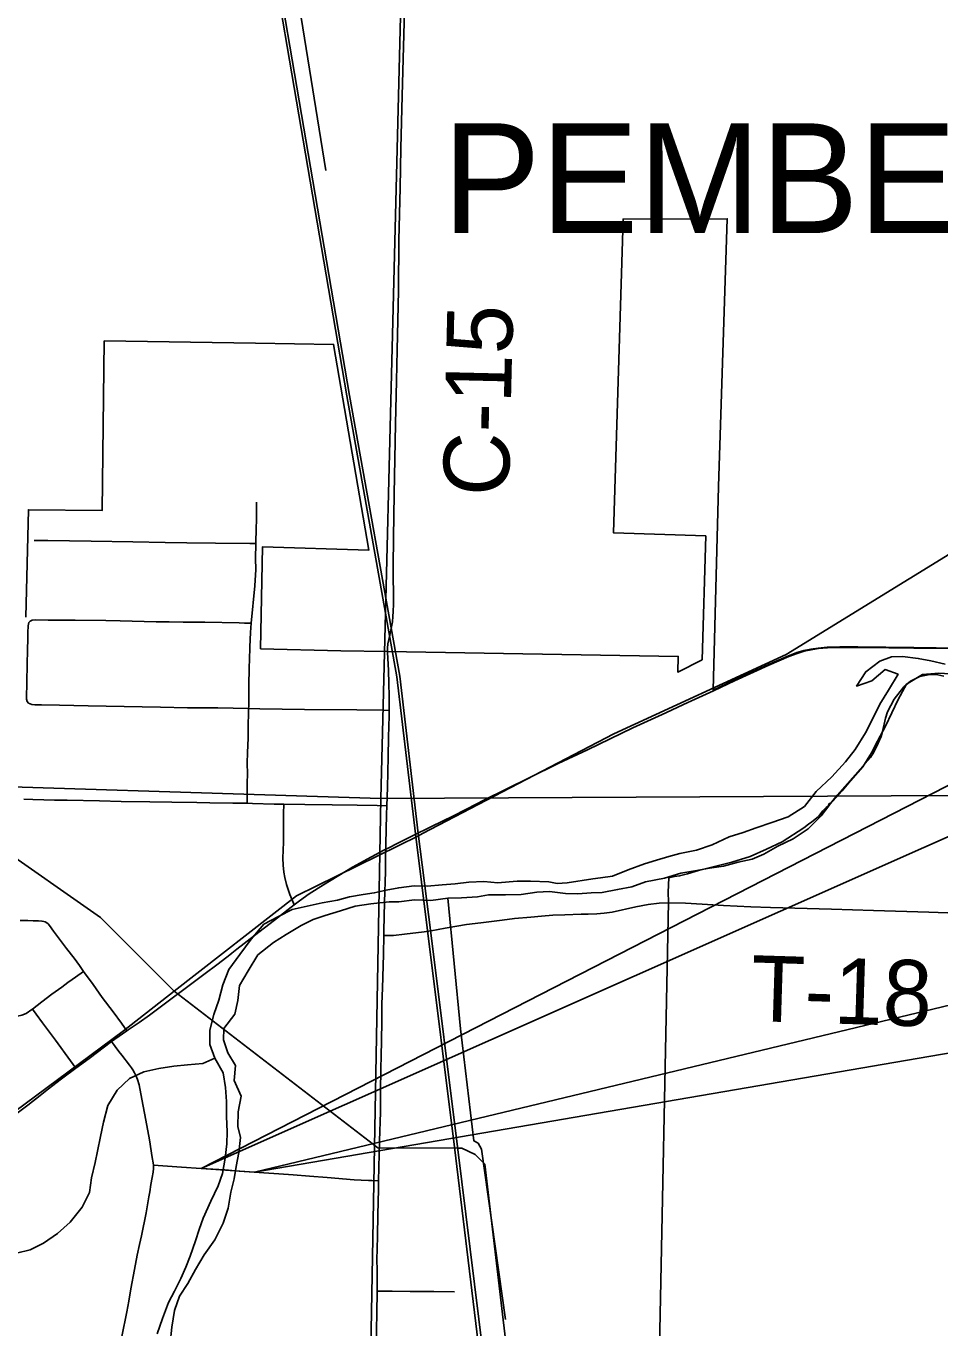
# Model space of a CAD drawing. Extents: x -8.3 to 42.1, y 0 to 22.
# Drawn here: x 5.562 to 6.351, y 16.882 to 18.005 of the extents above; entities that cross this region are included whole.
import ezdxf

# ---------------------------------------------------------------- set-up
doc = ezdxf.new("R2010")
doc.units = 0
for name, color, linetype in [('GM_X_City_Street', 7, 'Continuous'), ('GM_X_Corporation', 7, 'Continuous'), ('GM_X_Corporation_Text', 7, 'Continuous'), ('GM_X_County_Road', 7, 'Continuous'), ('GM_X_County_Road_Text', 7, 'Continuous'), ('GM_X_Major_River', 7, 'Continuous'), ('GM_X_Minor_River', 7, 'Continuous'), ('GM_X_Rail_Line', 7, 'Continuous'), ('GM_X_Section', 7, 'Continuous'), ('GM_X_State_Route', 7, 'Continuous'), ('GM_X_Township_Road', 7, 'Continuous'), ('GM_X_Township_Road_Text', 7, 'Continuous'), ('SH_Text', 7, 'Continuous')]:
    doc.layers.add(name, color=color, linetype=linetype)

msp = doc.modelspace()

# ---------------------------------------------------------------- linework, layer by layer
at = {"layer": 'GM_X_City_Street'}
for points in [[(5.7529, 17.3344), (5.7529, 17.3369), (5.7529, 17.3431), (5.753, 17.3474), (5.7531, 17.3525), (5.7533, 17.3588), (5.7531, 17.3697), (5.7534, 17.3773), (5.7536, 17.3852), (5.7538, 17.39), (5.7538, 17.3977), (5.7542, 17.4161), (5.7543, 17.4179), (5.7545, 17.4366), (5.7548, 17.4506), (5.7553, 17.468), (5.7553, 17.4693), (5.7558, 17.4817), (5.7564, 17.4896), (5.7595, 17.522), (5.7604, 17.5361), (5.7603, 17.5454), (5.7605, 17.5583), (5.7608, 17.5719), (5.7609, 17.5782), (5.7611, 17.594)], [(5.5693, 17.5609), (5.581, 17.5611), (5.6184, 17.5605), (5.6542, 17.56), (5.6822, 17.5594), (5.7009, 17.5591), (5.7258, 17.5586), (5.7554, 17.5583), (5.7605, 17.5583)], [(5.5644, 17.4206), (5.5631, 17.4221), (5.5626, 17.4241), (5.5629, 17.4397), (5.5634, 17.4672), (5.5637, 17.4755), (5.5637, 17.4816), (5.564, 17.4874), (5.5647, 17.4902), (5.5657, 17.4915)], [(5.5657, 17.4915), (5.5674, 17.4924), (5.5702, 17.4926), (5.5812, 17.4924), (5.6045, 17.4923), (5.631, 17.4919), (5.6434, 17.4917), (5.6744, 17.4909), (5.6857, 17.4908), (5.6978, 17.4907), (5.7165, 17.4905), (5.746, 17.49), (5.7507, 17.4898), (5.7564, 17.4896)], [(5.5644, 17.4206), (5.5671, 17.4195), (5.5699, 17.4192), (5.5755, 17.4192), (5.591, 17.4189), (5.6159, 17.4185), (5.6625, 17.4175), (5.6781, 17.4173), (5.7014, 17.4168), (5.7278, 17.4166), (5.7542, 17.4161), (5.7638, 17.4159), (5.8026, 17.4154), (5.8477, 17.4149), (5.8701, 17.4146), (5.8755, 17.4145)], [(5.5603, 17.3378), (5.568, 17.3376), (5.5774, 17.3374), (5.5867, 17.3372), (5.5976, 17.337), (5.6256, 17.3364), (5.6442, 17.336), (5.6691, 17.3355), (5.6881, 17.3354), (5.7096, 17.335), (5.7208, 17.3348), (5.7406, 17.3346), (5.7529, 17.3344), (5.7577, 17.3343), (5.7764, 17.3337), (5.7845, 17.3336), (5.8028, 17.3334), (5.8262, 17.3331), (5.8479, 17.3327), (5.8651, 17.3325), (5.8736, 17.3323)], [(5.7936, 17.2467), (5.7914, 17.2518), (5.7897, 17.2557), (5.7869, 17.2644), (5.7854, 17.2704), (5.7846, 17.2749), (5.784, 17.2809), (5.7838, 17.287), (5.7844, 17.3009), (5.7844, 17.3256), (5.7845, 17.3336)], [(5.6493, 17.1381), (5.6446, 17.1446), (5.6373, 17.1545), (5.628, 17.1669), (5.62, 17.1782), (5.6119, 17.1894), (5.6082, 17.1945), (5.6036, 17.2007), (5.597, 17.2092), (5.5859, 17.2241), (5.5823, 17.2291), (5.5813, 17.2303), (5.5801, 17.2312), (5.5788, 17.232), (5.5774, 17.2325), (5.5759, 17.2328), (5.5728, 17.2331), (5.5713, 17.233), (5.5682, 17.2331), (5.5638, 17.2332), (5.561, 17.2332), (5.557, 17.2333)], [(5.5549, 17.1508), (5.5585, 17.1516), (5.5623, 17.1532), (5.5671, 17.1564), (5.5679, 17.1569), (5.5758, 17.163), (5.5844, 17.1696), (5.5931, 17.1757), (5.5983, 17.1797), (5.602, 17.1824), (5.6098, 17.1878), (5.6119, 17.1894)], [(5.6052, 17.1058), (5.6005, 17.1123), (5.5877, 17.13), (5.5765, 17.145), (5.571, 17.1526), (5.5679, 17.1569)], [(5.6722, 17.0222), (5.6761, 17.0219), (5.6963, 17.0205), (5.7134, 17.0195), (5.7336, 17.0181), (5.746, 17.0172), (5.7803, 17.0148), (5.7927, 17.0139), (5.8068, 17.0127), (5.8221, 17.0116), (5.8454, 17.0097), (5.8515, 17.0093), (5.8576, 17.009), (5.8607, 17.0089), (5.8663, 17.0086)], [(5.8651, 16.9135), (5.8692, 16.9135), (5.8781, 16.9135), (5.8937, 16.9133), (5.9141, 16.9133), (5.9319, 16.9131)]]:
    msp.add_lwpolyline(points, dxfattribs=at)
at = {"layer": 'GM_X_Corporation'}
for points in [[(5.5621, 17.4948), (5.5642, 17.5875), (5.628, 17.5869), (5.6297, 17.7331), (5.7603, 17.7313), (5.8275, 17.7301), (5.858, 17.5527), (5.7662, 17.5555), (5.7645, 17.4676), (5.8339, 17.466), (5.8739, 17.4653), (6.1249, 17.4611), (6.1245, 17.4475), (6.1457, 17.4581), (6.1487, 17.5649), (6.0691, 17.5676), (6.0774, 17.8383), (6.1672, 17.8385), (6.1596, 17.6077), (6.1552, 17.4319), (6.1732, 17.4406), (6.2029, 17.4541), (6.22, 17.4615), (6.2274, 17.4643), (6.2334, 17.4661), (6.2395, 17.4674), (6.2457, 17.4683), (6.2535, 17.4689), (6.2644, 17.4693), (6.28, 17.4694), (6.3281, 17.4687), (6.3669, 17.4683)], [(6.354, 17.4441), (6.349, 17.4451), (6.3436, 17.4454), (6.3406, 17.4452), (6.3335, 17.4436), (6.3255, 17.4397), (6.3197, 17.4348), (6.3113, 17.4243), (6.3056, 17.4133), (6.3038, 17.4079), (6.3012, 17.3962), (6.3, 17.3921), (6.2987, 17.3887), (6.2976, 17.3861), (6.2947, 17.3802), (6.2929, 17.3771), (6.2929, 17.3766), (6.2923, 17.3763), (6.2908, 17.374), (6.2622, 17.3414), (6.2563, 17.3341), (6.2553, 17.3341), (6.2545, 17.3324), (6.2538, 17.3315), (6.2527, 17.3307), (6.2497, 17.328), (6.2459, 17.3231), (6.2443, 17.3214), (6.2403, 17.3183), (6.2374, 17.3164), (6.2334, 17.3131), (6.2147, 17.3012), (6.2011, 17.2948), (6.1871, 17.2885), (6.1712, 17.2837), (6.1423, 17.2764), (6.133, 17.2735), (6.1261, 17.2717), (6.1216, 17.2711), (6.1169, 17.2702), (6.1164, 17.2578), (6.1166, 17.2491), (6.1082, 16.8369)]]:
    msp.add_lwpolyline(points, dxfattribs=at)
at = {"layer": 'GM_X_County_Road'}
for points in [[(5.8741, 17.4647), (5.8741, 17.4681), (5.8744, 17.4718), (5.8761, 17.4793), (5.8783, 17.4909), (5.8787, 17.4955), (5.8791, 17.4997), (5.8793, 17.506), (5.879, 17.5386), (5.8794, 17.5635), (5.8798, 17.6009), (5.881, 17.6615), (5.8818, 17.6988), (5.8823, 17.7253), (5.8835, 17.7766), (5.884, 17.8201), (5.8851, 17.8652), (5.8857, 17.8995), (5.8868, 17.9445), (5.889, 18.0297)], [(5.8755, 17.4145), (5.8755, 17.4268), (5.8752, 17.4376), (5.8749, 17.449), (5.8741, 17.4647)], [(5.8736, 17.3323), (5.8741, 17.348), (5.8746, 17.3743), (5.875, 17.3913), (5.8755, 17.4098), (5.8755, 17.4145)], [(5.8726, 17.2947), (5.8727, 17.2991), (5.8733, 17.3248), (5.8736, 17.3323)], [(5.8708, 17.2204), (5.8708, 17.2243), (5.8715, 17.2492), (5.8723, 17.2756), (5.8723, 17.28), (5.8723, 17.2884), (5.8726, 17.2947)], [(5.8663, 17.0086), (5.8671, 17.0433), (5.8679, 17.0681), (5.8679, 17.085), (5.8683, 17.1065), (5.8685, 17.1157), (5.8691, 17.1452), (5.8693, 17.1607), (5.8696, 17.1685), (5.8699, 17.1747), (5.8705, 17.2041), (5.8708, 17.2204)], [(5.6532, 17.1062), (5.6516, 17.1085), (5.6448, 17.1171), (5.6423, 17.1203), (5.6359, 17.129)], [(5.6722, 17.0222), (5.672, 17.0242), (5.6711, 17.0288), (5.6686, 17.0441), (5.6664, 17.0564), (5.6613, 17.0839), (5.6597, 17.0915), (5.6584, 17.0961), (5.6573, 17.0991), (5.6559, 17.1019), (5.6543, 17.1046), (5.6532, 17.1062)], [(5.6449, 16.8745), (5.6492, 16.8958), (5.6508, 16.905), (5.6527, 16.9157), (5.6559, 16.9324), (5.6582, 16.9446), (5.6601, 16.9537), (5.6617, 16.9613), (5.6657, 16.9811), (5.6682, 16.9948), (5.6689, 16.9993), (5.6699, 17.0055), (5.6709, 17.0116), (5.6718, 17.0162), (5.6722, 17.0194), (5.6722, 17.0222)], [(5.8651, 16.9135), (5.8651, 16.9176), (5.8652, 16.9316), (5.865, 16.9409), (5.8651, 16.9502), (5.8654, 16.961), (5.8656, 16.9796), (5.8662, 17.0014), (5.8663, 17.0086)], [(5.8638, 16.8392), (5.8649, 16.8943), (5.8651, 16.9135)]]:
    msp.add_lwpolyline(points, dxfattribs=at)
at = {"layer": 'GM_X_Major_River'}
for points in [[(6.3554, 17.4545), (6.3429, 17.4571), (6.332, 17.4593), (6.3184, 17.4611), (6.3089, 17.4606), (6.299, 17.457), (6.2867, 17.4478), (6.2788, 17.4355), (6.2921, 17.4401), (6.3034, 17.4497), (6.3146, 17.4456), (6.3063, 17.4318), (6.2988, 17.4198), (6.2929, 17.4075), (6.2865, 17.3951), (6.2777, 17.3809), (6.2692, 17.3701), (6.2575, 17.3571), (6.244, 17.3445), (6.2338, 17.3315), (6.2199, 17.3227), (6.2058, 17.3177), (6.1921, 17.3131), (6.181, 17.3092), (6.1688, 17.3053), (6.1542, 17.2985)], [(5.9759, 17.2554), (5.9895, 17.2558), (6.0028, 17.2578), (6.0138, 17.2583), (6.0277, 17.2567), (6.0383, 17.2562), (6.0498, 17.257), (6.0593, 17.2575), (6.0726, 17.2599), (6.0848, 17.2622), (6.0966, 17.2665), (6.113, 17.2699), (6.1271, 17.2741), (6.1393, 17.2761), (6.1518, 17.2784), (6.164, 17.28), (6.1766, 17.2835), (6.1887, 17.2863), (6.1987, 17.2906), (6.211, 17.2975), (6.224, 17.3036), (6.2371, 17.3124), (6.2484, 17.3236), (6.2558, 17.3332), (6.2663, 17.3451), (6.2737, 17.3538), (6.2843, 17.3658), (6.2917, 17.3779), (6.2969, 17.388), (6.3037, 17.4008), (6.3148, 17.424), (6.322, 17.4371), (6.3358, 17.4455), (6.3499, 17.4467), (6.3597, 17.4461)], [(6.1542, 17.2985), (6.1408, 17.2939), (6.1264, 17.2912), (6.1168, 17.2884), (6.1062, 17.2852), (6.0959, 17.2821), (6.0817, 17.2771), (6.0683, 17.2714), (6.0579, 17.2702), (6.0512, 17.2693), (6.029, 17.2658), (6.0206, 17.2653), (6.0133, 17.2666), (5.9975, 17.2671), (5.9859, 17.2671), (5.9792, 17.2667), (5.9693, 17.2658), (5.9573, 17.2668), (5.9444, 17.2664), (5.9326, 17.2648), (5.9212, 17.2639), (5.9082, 17.2628), (5.8971, 17.2631), (5.8838, 17.2615), (5.873, 17.2594), (5.8627, 17.257), (5.8532, 17.2557), (5.8414, 17.2537), (5.8308, 17.2509), (5.8178, 17.2486), (5.7919, 17.2428), (5.78, 17.2366), (5.7674, 17.2301), (5.7564, 17.2171), (5.7467, 17.204), (5.7372, 17.191), (5.732, 17.1778), (5.7286, 17.1646), (5.7242, 17.1522), (5.7208, 17.1386), (5.7209, 17.1264), (5.7251, 17.1146)], [(5.6865, 16.8688), (5.6879, 16.8825), (5.6902, 16.8968), (5.6947, 16.9092), (5.7017, 16.9201), (5.7085, 16.9324), (5.716, 16.9448), (5.725, 16.9578), (5.7322, 16.9721), (5.7367, 16.9853), (5.7389, 16.9989), (5.7419, 17.0106), (5.7436, 17.0212), (5.7458, 17.0332), (5.7473, 17.0461), (5.7449, 17.0557), (5.7452, 17.0682), (5.7478, 17.0818), (5.7417, 17.0952), (5.7428, 17.1081), (5.7362, 17.1192), (5.7327, 17.1303), (5.733, 17.1402), (5.7423, 17.1525), (5.7449, 17.1642), (5.7464, 17.1771), (5.7539, 17.1898), (5.7622, 17.2036), (5.7757, 17.2143), (5.7865, 17.2213), (5.7995, 17.2289), (5.8099, 17.234), (5.8202, 17.2375), (5.8336, 17.2417), (5.8461, 17.2456), (5.8598, 17.2476), (5.8754, 17.2493), (5.8838, 17.2493), (5.8974, 17.2512), (5.9114, 17.2505), (5.926, 17.2524), (5.938, 17.2529), (5.9516, 17.2537), (5.9611, 17.2554), (5.9759, 17.2554)], [(5.7251, 17.1146), (5.7148, 17.1099), (5.7015, 17.1087), (5.6897, 17.1075), (5.6768, 17.1055), (5.6639, 17.1028), (5.6516, 17.097), (5.6407, 17.087), (5.6328, 17.0736), (5.6291, 17.0592), (5.6265, 17.0471), (5.6239, 17.0343), (5.6218, 17.0245), (5.6188, 17.0113), (5.617, 16.9988), (5.6106, 16.986), (5.6004, 16.973), (5.5892, 16.9634), (5.5773, 16.955), (5.5658, 16.9492), (5.554, 16.9464)], [(5.7251, 17.1146), (5.7324, 17.1019), (5.7343, 17.0893), (5.7352, 17.0771), (5.7352, 17.0642), (5.7357, 17.0509), (5.7354, 17.0407), (5.734, 17.0282), (5.7317, 17.015), (5.7281, 17.0045), (5.7217, 16.9913), (5.7151, 16.9765), (5.7116, 16.9669), (5.7083, 16.9571), (5.7039, 16.9439), (5.7002, 16.9342), (5.6958, 16.9244), (5.6902, 16.9135), (5.6851, 16.9038), (5.6798, 16.8899), (5.6753, 16.8767)]]:
    msp.add_lwpolyline(points, dxfattribs=at)
at = {"layer": 'GM_X_Minor_River'}
for points in [[(5.7602, 18.2335), (5.7798, 18.1277), (5.7996, 18.0122), (5.821, 17.88)], [(5.926, 17.2524), (5.9371, 17.1398), (5.9487, 17.0431), (5.9524, 17.0411), (5.9553, 17.0361), (5.9759, 16.8891)]]:
    msp.add_lwpolyline(points, dxfattribs=at)
at = {"layer": 'GM_X_Rail_Line'}
for p, q in [((5.9007, 17.3063), (5.9044, 17.3082)), ((5.9344, 17.037), (5.9383, 17.037))]:
    msp.add_line(p, q, dxfattribs=at)
for points in [[(4.4602, 20.9), (4.4279, 19.896), (4.4279, 19.7141), (4.5329, 19.1719), (4.7134, 18.2287), (4.7298, 18.1615), (4.7562, 18.1061), (4.7924, 18.0389), (4.852, 17.9646), (5.1115, 17.6457), (5.209, 17.5403), (5.4439, 17.3636), (5.6263, 17.2359), (5.6901, 17.1722)], [(5.9654, 16.7643), (5.9567, 16.8335), (5.932, 17.0379), (5.9087, 17.2246), (5.8981, 17.3081), (5.8822, 17.4435), (5.8389, 17.6857), (5.7322, 18.3104), (5.5565, 19.3262), (5.427, 20.0822), (5.2858, 20.9)], [(6.2899, 14.1), (6.2222, 14.6512), (6.0176, 16.3351), (5.9781, 16.679), (5.9602, 16.8313), (5.9345, 17.0381), (5.9111, 17.2249), (5.9006, 17.3084), (5.8846, 17.4439), (5.8413, 17.6862), (5.7347, 18.3108), (5.559, 19.3267), (5.4294, 20.0826), (5.2883, 20.9)], [(5.9044, 17.3082), (6.0693, 17.3942), (6.218, 17.4628), (6.6389, 17.7213), (6.9437, 17.9671), (7.085, 17.9703), (7.2495, 18.0325), (7.9103, 18.3409)], [(5.6901, 17.1722), (5.7955, 17.2545), (5.9007, 17.3063)], [(5.3428, 16.9248), (5.4853, 17.0187), (5.6464, 17.1381), (5.6901, 17.1722)], [(5.6901, 17.1722), (5.8656, 17.0371), (5.9344, 17.037)], [(5.9383, 17.037), (5.9498, 17.0314), (5.958, 17.0231), (6.2364, 14.6613)]]:
    msp.add_lwpolyline(points, dxfattribs=at)
at = {"layer": 'GM_X_Section'}
for points in [[(4.9147, 18.3251), (5.8932, 18.3221), (5.8682, 17.3386), (5.431, 17.3522), (4.866, 17.3546), (4.8893, 18.3249)], [(5.9121, 18.3219), (6.8731, 18.3158), (6.8593, 17.3438), (5.8682, 17.3386), (5.8932, 18.3221)], [(5.8682, 17.3386), (5.8503, 16.3424), (4.8464, 16.3395), (4.866, 17.3546), (5.431, 17.3522)], [(6.8593, 17.3438), (6.8436, 16.3404), (5.8503, 16.3424), (5.8682, 17.3386)]]:
    msp.add_lwpolyline(points, close=True, dxfattribs=at)
at = {"layer": 'GM_X_State_Route'}
for points in [[(6.2852, 17.4687), (6.3283, 17.4682), (6.3671, 17.4678), (6.392, 17.4677), (6.4509, 17.4673), (6.4773, 17.4672), (6.4991, 17.4669), (6.5162, 17.4666), (6.5441, 17.4658), (6.572, 17.4654), (6.586, 17.4655), (6.5952, 17.466), (6.6013, 17.4668), (6.6058, 17.4678), (6.6117, 17.4695), (6.6174, 17.4716), (6.6216, 17.4735), (6.6257, 17.4756), (6.6296, 17.4781), (6.6333, 17.4807), (6.6374, 17.4841), (6.6404, 17.4869)], [(6.1554, 17.4313), (6.1734, 17.4401), (6.2031, 17.4536), (6.2203, 17.461), (6.2276, 17.4637), (6.2336, 17.4655), (6.2397, 17.4668), (6.2459, 17.4678), (6.2537, 17.4684), (6.2646, 17.4688), (6.2802, 17.4688), (6.2852, 17.4687)], [(6.1295, 17.4196), (6.1395, 17.4242), (6.1554, 17.4313)], [(5.9512, 17.334), (5.9573, 17.3371), (5.9963, 17.3564), (6.0214, 17.3687), (6.0467, 17.3806), (6.0663, 17.39), (6.0859, 17.3995), (6.1142, 17.4124), (6.1295, 17.4196)], [(5.8709, 17.2938), (5.8726, 17.2947), (5.874, 17.2955), (5.8837, 17.3004), (5.8963, 17.3065), (5.9116, 17.314), (5.9311, 17.3236), (5.9512, 17.334)], [(5.7398, 17.2051), (5.7442, 17.2086), (5.7594, 17.2202), (5.7765, 17.2336), (5.7936, 17.2467), (5.7982, 17.2502), (5.8066, 17.2562), (5.8188, 17.2641), (5.832, 17.2721), (5.844, 17.2793), (5.8603, 17.2882), (5.8709, 17.2938)], [(5.5546, 17.0672), (5.5636, 17.0741), (5.5744, 17.0823), (5.5815, 17.0881), (5.5927, 17.0967), (5.6052, 17.1058), (5.6166, 17.1142), (5.6359, 17.129), (5.6493, 17.1381), (5.6504, 17.1389), (5.6599, 17.1453), (5.6686, 17.1517), (5.7155, 17.1867), (5.7279, 17.1959), (5.7381, 17.2038), (5.7398, 17.2051)]]:
    msp.add_lwpolyline(points, dxfattribs=at)
at = {"layer": 'GM_X_Township_Road'}
for points in [[(5.8708, 17.2204), (5.8731, 17.2203), (5.8793, 17.2202), (5.8888, 17.2215), (5.9056, 17.2236), (5.9117, 17.2245), (5.9239, 17.2266), (5.9423, 17.2297), (5.9546, 17.2314), (5.9731, 17.2336), (5.9838, 17.2349), (5.9977, 17.2362), (6.0071, 17.2369), (6.0167, 17.238), (6.0272, 17.2383), (6.0411, 17.2387), (6.0472, 17.2388), (6.0546, 17.2389), (6.061, 17.2397), (6.0678, 17.2406), (6.0884, 17.2452), (6.0991, 17.247), (6.1084, 17.2481), (6.1168, 17.2486)], [(6.1168, 17.2486), (6.1312, 17.2482), (6.1455, 17.2474), (6.1641, 17.2463), (6.1877, 17.2452), (6.2045, 17.2446), (6.2573, 17.243), (6.2934, 17.2419), (6.3412, 17.2405), (6.3655, 17.2396)]]:
    msp.add_lwpolyline(points, dxfattribs=at)
at = {"layer": 'SH_Text'}
msp.add_line((5.7134, 17.0195), (5.7594, 17.0162), dxfattribs=at)
for points in [[(9.5811, 19.002), (5.7134, 17.0195), (9.5811, 18.737)], [(9.5811, 17.9343), (5.7594, 17.0162), (9.5811, 17.6715)]]:
    msp.add_lwpolyline(points, close=True, dxfattribs=at)

# ---------------------------------------------------------------- texts
at = {"layer": 'GM_X_Corporation_Text'}
msp.add_text('PEMBERVILLE', height=0.094697, rotation=0, dxfattribs=at).set_placement((5.9217, 17.8261))
at = {"layer": 'GM_X_County_Road_Text'}
msp.add_text('C-15', height=0.05682, rotation=88.6573, dxfattribs=at).set_placement((5.9787, 17.5989))
at = {"layer": 'GM_X_Township_Road_Text'}
msp.add_text('T-18', height=0.05682, rotation=358.2329, dxfattribs=at).set_placement((6.1869, 17.1466))

doc.saveas('drawing.dxf')
